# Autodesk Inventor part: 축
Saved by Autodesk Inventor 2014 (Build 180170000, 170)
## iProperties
Created: 2025-10
Part Number: 축
Material: 일반
Document SubType Name: Modeling
Designer: dg
Density: 1 g/cm^3
Appearance: 기본값
Author: dg
Author: jhkim
Creation Date: 2025-10-01
Sending System: Autodesk Inventor 2026
Preprocessor: ST-DEVELOPER v20.1
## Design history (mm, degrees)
node "축1"
node "솔리드1"
node "기준1"
